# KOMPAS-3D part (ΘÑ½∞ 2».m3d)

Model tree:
1. Эскиз:1
2. Операция выдавливания:1
     Расстояние 1 = 2
3. Эскиз:2
4. Операция выдавливания:2
     Расстояние 1 = 5
5. Эскиз:3
6. Операция выдавливания:3
     Расстояние 1 = 2
7. Эскиз:4
8. Операция выдавливания:4
     Расстояние 1 = 78
9. Эскиз:5
10. Операция выдавливания:5
     Расстояние 1 = 2
11. Эскиз:6
12. Операция выдавливания:6
     Расстояние 1 = 4.5
13. Эскиз:7
14. Операция выдавливания:7
     Расстояние 1 = 2
15. Скругление:1
     Радиус = 1
16. Скругление:2
     Радиус = 1
17. Эскиз:8
18. Вырезать элемент выдавливания:1
     Расстояние 1 = 10; Угол 1 = 35
19. Эскиз:9
20. Вырезать элемент выдавливания:2
     Расстояние 1 = 10; Угол 1 = 35
21. Эскиз:10
22. Вырезать элемент выдавливания:3
     Расстояние 2 = 22; Расстояние 1 = 22; Угол 1 = 35
23. Эскиз:11
24. Вырезать элемент выдавливания:4
     Расстояние 2 = 2; Расстояние 1 = 2
25. Эскиз:12
26. Вырезать элемент выдавливания:5
     Расстояние 2 = 2; Расстояние 1 = 2; Угол 1 = 35
27. Эскиз:13
28. Вырезать элемент выдавливания:6
     Расстояние 2 = 2; Расстояние 1 = 122
29. Эскиз:14
30. Вырезать элемент выдавливания:7
     Расстояние 2 = 100; Расстояние 1 = 60
